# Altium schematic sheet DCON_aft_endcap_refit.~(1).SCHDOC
size B; Organization: Monterey Bay Aquarium Research Institute; Address1: 7700 Sandholdt Rd; Address2: Moss Landing, CA 95039-9644; CompanyName: MBARI
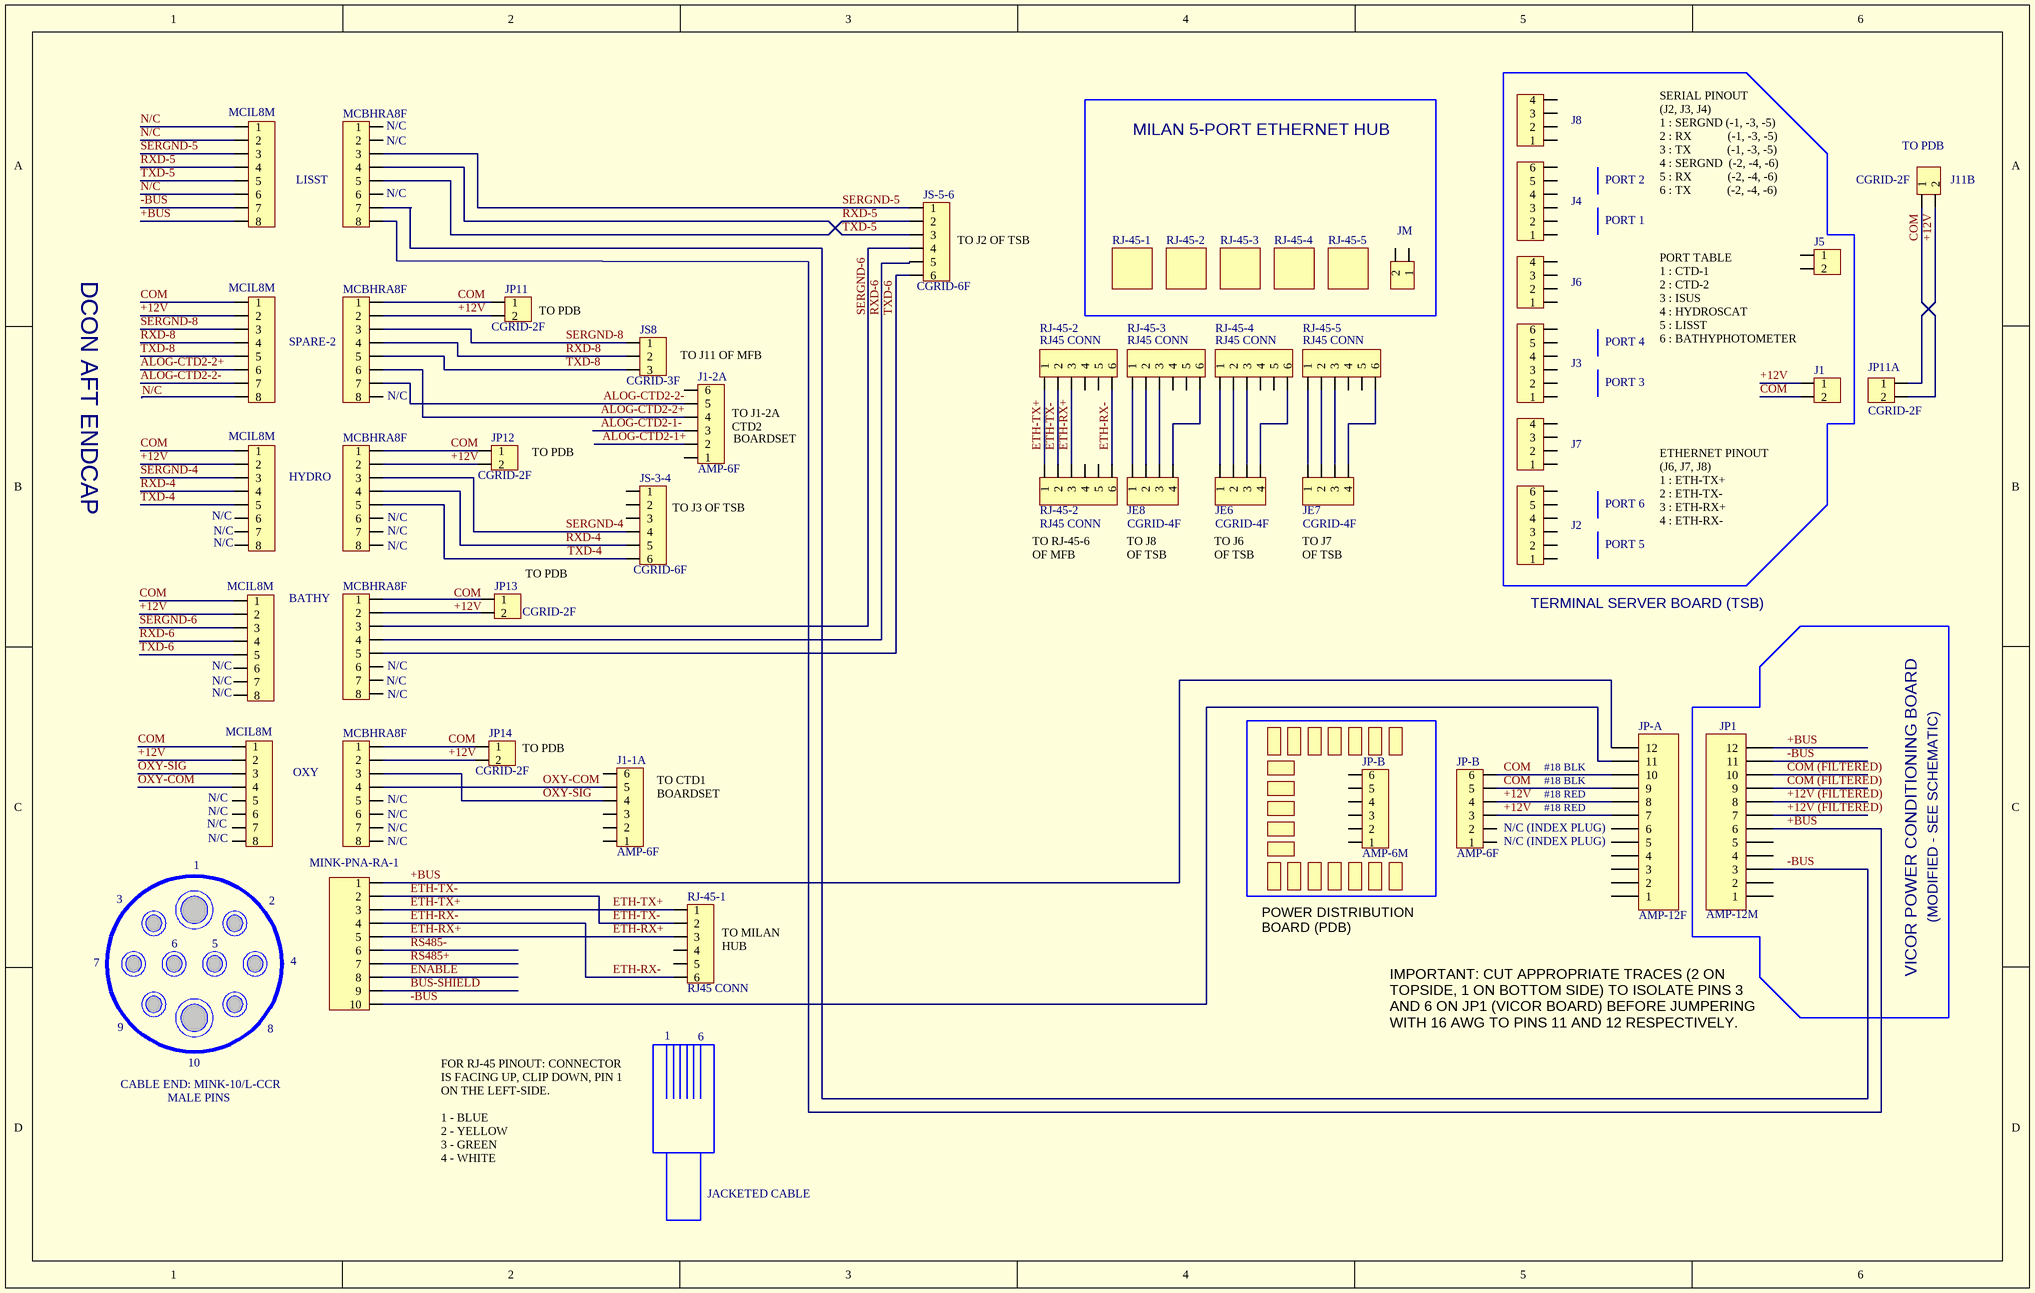
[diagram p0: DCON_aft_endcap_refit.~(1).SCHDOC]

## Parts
(Parts that share a designator on the sheet are numbered #1, #2 ... from top to bottom, then left to right.)
?#1  MCIL8M  [SIP8]
?#2  MCBHRA8F  [SIP8]
?#3  MCIL8M  [SIP8]
?#4  MCBHRA8F  [SIP8]
?#5  MCIL8M  [SIP8]
?#6  MCBHRA8F  [SIP8]
?#7  MCIL8M  [SIP8]
?#8  MCBHRA8F  [SIP8]
?#9  MCIL8M  [SIP8]
?#10  MCBHRA8F  [SIP8]
J1  CGRID-2M  [SIP7]  (value not drawn)
J1-1A  AMP-6F  [SIP7]
J1-2A  AMP-6F  [SIP7]
J2  CGRID-6M  [SIP7]  (value not drawn)
J3  CGRID-6M  [SIP7]  (value not drawn)
J4  CGRID-6M  [SIP7]  (value not drawn)
J5  CGRID-2M  [SIP7]  (value not drawn)
J6  CGRID-4M  [SIP7]  (value not drawn)
J7  CGRID-4M  [SIP7]  (value not drawn)
J8  CGRID-4M  [SIP7]  (value not drawn)
J11B  CGRID-2F  [SIP7]
JE6  CGRID-4F  [SIP6]
JE7  CGRID-4F  [SIP6]
JE8  CGRID-4F  [SIP6]
JM  PLUG  [HDR1X12]  (value not drawn)
JP1  AMP-12M  [HDR1X12]
JP11  CGRID-2F  [HDR1X12]
JP11A  CGRID-2F  [SIP7]
JP12  CGRID-2F  [HDR1X12]
JP13  CGRID-2F  [HDR1X12]
JP14  CGRID-2F  [HDR1X12]
JP-A  AMP-12F  [HDR1X12]
JP-B#1  AMP-6M  [HDR1X12]
JP-B#2  AMP-6F  [HDR1X12]
JS8  CGRID-3F  [HDR1X12]
JS-3-4  CGRID-6F  [HDR1X12]
JS-5-6  CGRID-6F  [HDR1X12]
MINK-PNA-RA-1  SEACON  [SIP7]  (value not drawn)
RJ-45-1  RJ45 CONN  [HDR1X12]
RJ-45-2#1  RJ45 CONN  [SIP6]
RJ-45-2#2  RJ45 CONN  [SIP6]
RJ-45-3  RJ45 CONN  [SIP6]
RJ-45-4  RJ45 CONN  [SIP6]
RJ-45-5  RJ45 CONN  [SIP6]

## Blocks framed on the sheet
MILAN 5-PORT ETHERNET HUB: JM
VICOR POWER CONDITIONING BOARD: JP1

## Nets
+12V: ?#3.2 ?#4.2 ?#5.2 ?#6.2 ?#7.2 ?#9.2 ?#10.2 J1.1 J11B.2 JP11.2 JP11A.1 JP12.2 JP14.2 JP-A.7 JP-A.8 JP-B#2.3 JP-B#2.4
+12V (FILTERED): JP1.7 JP1.8
+BUS: ?#1.8 ?#2.8 JP1.6 JP1.12 JP-A.12 MINK-PNA-RA-1.1
-BUS: ?#1.7 ?#2.7 JP1.3 JP1.11 JP-A.11 MINK-PNA-RA-1.10
ALOG-CTD2-1+: J1-2A.2
ALOG-CTD2-1-: J1-2A.3
ALOG-CTD2-2+: ?#3.6 ?#4.6 J1-2A.4
ALOG-CTD2-2-: ?#3.7 ?#4.7 J1-2A.5
BUS-SHIELD: MINK-PNA-RA-1.9
COM: ?#3.1 ?#4.1 ?#5.1 ?#6.1 ?#7.1 ?#9.1 ?#10.1 J1.2 J11B.1 JP11.1 JP11A.2 JP12.1 JP14.1 JP-A.9 JP-A.10 JP-B#2.5 JP-B#2.6
COM (FILTERED): JP1.9 JP1.10
ENABLE: MINK-PNA-RA-1.8
ETH-RX+: MINK-PNA-RA-1.5 RJ-45-1.3 RJ-45-2#1.3 RJ-45-2#2.3
ETH-RX-: MINK-PNA-RA-1.4 RJ-45-1.6 RJ-45-2#1.6 RJ-45-2#2.6
ETH-TX+: MINK-PNA-RA-1.3 RJ-45-1.1 RJ-45-2#1.1 RJ-45-2#2.1
ETH-TX-: MINK-PNA-RA-1.2 RJ-45-1.2 RJ-45-2#1.2 RJ-45-2#2.2
N/C: ?#1.1 ?#1.2 ?#1.6 ?#3.8
OXY-COM: ?#9.4 ?#10.4 J1-1A.5
OXY-SIG: ?#9.3 ?#10.3 J1-1A.4
RS485+: MINK-PNA-RA-1.7
RS485-: MINK-PNA-RA-1.6
RXD-4: ?#5.4 ?#6.4 JS-3-4.5
RXD-5: ?#1.4 ?#2.5 JS-5-6.2
RXD-6: ?#7.4
RXD-8: ?#3.4 ?#4.4 JS8.2
SERGND-4: ?#5.3 ?#6.3 JS-3-4.4
SERGND-5: ?#1.3 ?#2.3 JS-5-6.1
SERGND-6: ?#7.3
SERGND-8: ?#3.3 ?#4.3 JS8.1
TXD-4: ?#5.5 ?#6.5 JS-3-4.6
TXD-5: ?#1.5 ?#2.4 JS-5-6.3
TXD-6: ?#7.5 ?#8.5 JS-5-6.6
TXD-8: ?#3.5 ?#4.5 JS8.3
Net?#8_1: ?#8.1 JP13.1
Net?#8_2: ?#8.2 JP13.2
Net?#8_3: ?#8.3 JS-5-6.4
Net?#8_4: ?#8.4 JS-5-6.5
NetJE6_1: JE6.1 RJ-45-4.1
NetJE6_2: JE6.2 RJ-45-4.2
NetJE6_3: JE6.3 RJ-45-4.3
NetJE6_4: JE6.4 RJ-45-4.6
NetJE7_1: JE7.1 RJ-45-5.1
NetJE7_2: JE7.2 RJ-45-5.2
NetJE7_3: JE7.3 RJ-45-5.3
NetJE7_4: JE7.4 RJ-45-5.6
NetJE8_1: JE8.1 RJ-45-3.1
NetJE8_2: JE8.2 RJ-45-3.2
NetJE8_3: JE8.3 RJ-45-3.3
NetJE8_4: JE8.4 RJ-45-3.6

Not connected (* = marked no-connect by the designer): ?#2 1 2 6; ?#4 8; ?#5 6 7 8; ?#6 6 7 8; ?#7 6 7 8; ?#8 6 7 8; ?#9 5 6 7 8; ?#10 5 6 7 8; J1-1A 1 2 3 6; J1-2A 1 6; J2 1 2 3 4 5 6; J3 1 2 3 4 5 6; J4 1 2 3 4 5 6; J5 1 2; J6 1 2 3 4; J7 1 2 3 4; J8 1 2 3 4; JM 1 2; JP1 1 2 4 5; JP-A 1 2 3 4 5 6; JP-B#1 1 2 3 4 5 6; JP-B#2 1 2; JS-3-4 1 2 3; RJ-45-1 4 5; RJ-45-2#1 4 5; RJ-45-2#2 4 5; RJ-45-3 4 5; RJ-45-4 4 5; RJ-45-5 4 5

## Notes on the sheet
- N/C
- (near J11B) TO PDB
- LISST
- PORT 2
- PORT 1
- (near J5) SERIAL PINOUT
  (J2, J3, J4)
  1 : SERGND (-1, -3, -5)
  2 : RX            (-1, -3, -5)
  3 : TX            (-1, -3, -5)
  4 : SERGND  (-2, -4, -6)
  5 : RX            (-2, -4, -6)
  6 : TX            (-2, -4, -6)
- DCON AFT ENDCAP
- (near JS-5-6) TO J2 OF TSB
- RJ-45-1
- RJ-45-2
- RJ-45-3
- RJ-45-4
- (near JM) RJ-45-5
- SPARE-2
- (near JP11) TO PDB
- TO J11 OF MFB
- PORT 4
- (near J5) PORT TABLE
  1 : CTD-1
  2 : CTD-2
  3 : ISUS
  4 : HYDROSCAT
  5 : LISST
  6 : BATHYPHOTOMETER
- (near J1-2A) TO J1-2A
- (near J1-2A) CTD2
- PORT 3
- HYDRO
- (near JP12) TO PDB
- (near J1-2A) BOARDSET
- PORT 6
- TO J3 OF TSB
- PORT 5
- (near J1) ETHERNET PINOUT
  (J6, J7, J8)
  1 : ETH-TX+
  2 : ETH-TX-
  3 : ETH-RX+
  4 : ETH-RX-
- BATHY
- (near JP13) TO PDB
- TO RJ-45-6
  OF MFB
- TO J8
  OF TSB
- TO J6
  OF TSB
- TO J7
  OF TSB
- (near J2) TERMINAL SERVER BOARD (TSB)
- OXY
- (near JP14) TO PDB
- #18 BLK
- (near MINK-PNA-RA-1) N/C
- (near J1-1A) TO CTD1
  BOARDSET
- (near JP-B#2) N/C (INDEX PLUG)
- #18 RED
- 3
- 1
- 2
- 7
- 6
- 5
- 4
- (near RJ-45-1) TO MILAN
  HUB
- POWER DISTRIBUTION
  BOARD (PDB)
- (MODIFIED - SEE SCHEMATIC)
- 9
- 8
- IMPORTANT: CUT APPROPRIATE TRACES (2 ON
  TOPSIDE, 1 ON BOTTOM SIDE) TO ISOLATE PINS 3
  AND 6 ON JP1 (VICOR BOARD) BEFORE JUMPERING
  WITH 16 AWG TO PINS 11 AND 12 RESPECTIVELY.
- CABLE END: MINK-10/L-CCR
- MALE PINS
- 10
- FOR RJ-45 PINOUT: CONNECTOR
  IS FACING UP, CLIP DOWN, PIN 1
  ON THE LEFT-SIDE.
  1 - BLUE
  2 - YELLOW
  3 - GREEN
  4 - WHITE
- JACKETED CABLE
- Labels drawn without touching a wire or pin: +12V, COM, RXD-6, SERGND-6

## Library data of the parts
?#1-?#10 = CON8: Connector; ManufPartNo: MCIL8M molded to 24"  8/20 SO Cable; Manufacturer: Subconn
J1 J5 J11B JM JP11 JP11A JP12-JP14 = CON2: Connector
J1-1A J1-2A J2-J4 JP-B#1 JP-B#2 JS-3-4 JS-5-6 RJ-45-1 RJ-45-2#1 RJ-45-2#2 RJ-45-3-RJ-45-5 = CON6: Connector
J6-J8 JE6-JE8 = CON4: Connector
JP1 JP-A = Header 12: Header, 12-Pin; Manufacturer: Generic Components; Class I: Connector
JS8 = CON3: Connector
MINK-PNA-RA-1 = CON10: Connector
